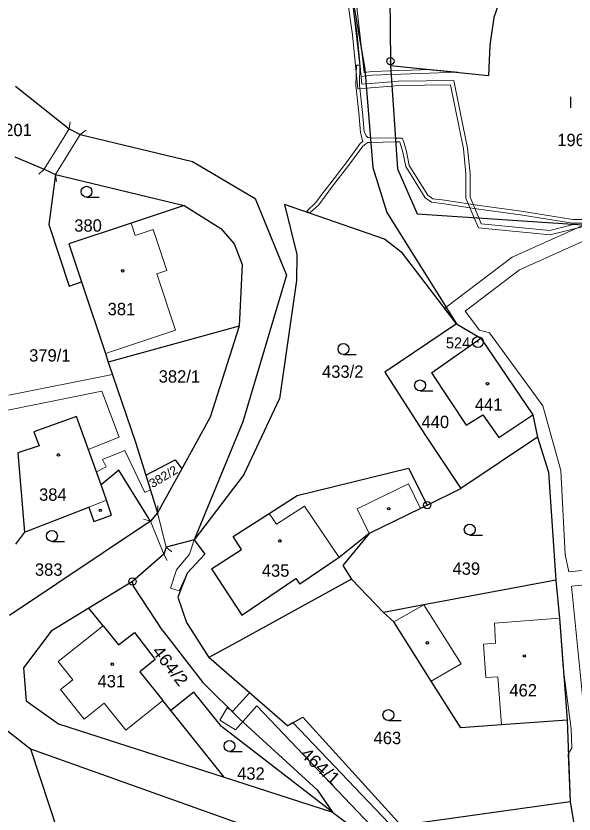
# Model space of a CAD drawing. Extents: x -727701 to -724405, y -960481 to -957284.
# Drawn here: x -726812.2 to -726735.5, y -958317.7 to -958207.9 of the extents above; entities that cross this region are included whole.
import ezdxf
from ezdxf.enums import TextEntityAlignment as Align

# ---------------------------------------------------------------- set-up
doc = ezdxf.new("R2010")
doc.units = 0
doc.header["$LTSCALE"] = 0.68
for name, color, linetype, lineweight in [('1', 7, 'Continuous', 25), ('13', 7, 'Continuous', 13), ('3', 7, 'Continuous', 25), ('4', 7, 'Continuous', 13), ('5', 7, 'Continuous', 25), ('8', 7, 'Continuous', 25)]:
    doc.layers.add(name, color=color, linetype=linetype, lineweight=lineweight)
doc.layers.add('2', color=7, linetype='Continuous')

msp = doc.modelspace()

# ---------------------------------------------------------------- linework, layer by layer
at = {"layer": '1'}
for p, q in [((-726767.89, -958194.1), (-726764.26, -958215.23)), ((-726760.86, -958201.3), (-726760.73, -958214.13)), ((-726744.52, -958202.36), (-726746.5, -958208.13)), ((-726746.5, -958208.13), (-726747.05, -958211.93)), ((-726747.05, -958211.93), (-726747.24, -958216.07)), ((-726760.73, -958214.13), (-726760.72, -958214.72)), ((-726764.26, -958215.23), (-726763.16, -958228.74)), ((-726760.72, -958214.72), (-726759.77, -958228.94)), ((-726760.72, -958214.72), (-726747.24, -958216.07)), ((-726812.27, -958217.58), (-726804.87, -958223.44)), ((-726804.87, -958223.44), (-726803.36, -958224.2)), ((-726803.36, -958224.2), (-726787.95, -958227.94)), ((-726812.38, -958227.27), (-726808.33, -958228.97)), ((-726787.95, -958227.94), (-726779.32, -958233.01)), ((-726808.33, -958228.97), (-726806.77, -958229.7)), ((-726763.16, -958228.74), (-726761.24, -958234.92)), ((-726759.77, -958228.94), (-726757.07, -958235.13)), ((-726806.77, -958229.7), (-726807.67, -958236.58)), ((-726806.77, -958229.7), (-726789.09, -958233.96)), ((-726779.32, -958233.01), (-726775.03, -958243.57)), ((-726775.3, -958233.84), (-726773.57, -958240.72)), ((-726761.56, -958238.62), (-726775.3, -958233.84)), ((-726789.09, -958233.96), (-726796.37, -958236.41)), ((-726789.09, -958233.96), (-726784.04, -958237.15)), ((-726761.24, -958234.92), (-726751.63, -958250.24)), ((-726757.07, -958235.13), (-726729.4, -958236.95)), ((-726807.67, -958236.58), (-726804.91, -958245.08)), ((-726796.37, -958236.41), (-726804.92, -958239.26)), ((-726784.04, -958237.15), (-726782.22, -958239.25)), ((-726804.92, -958239.26), (-726803.18, -958244.48)), ((-726782.22, -958239.25), (-726781.09, -958242.09)), ((-726759.08, -958240.55), (-726761.56, -958238.62)), ((-726773.57, -958240.72), (-726773.64, -958244.31)), ((-726751.63, -958250.24), (-726759.08, -958240.55)), ((-726781.09, -958242.09), (-726781.52, -958250.57)), ((-726775.03, -958243.57), (-726781, -958263.75)), ((-726804.91, -958245.08), (-726803.18, -958244.48)), ((-726803.18, -958244.48), (-726799.91, -958254.32)), ((-726773.64, -958244.31), (-726775.98, -958260.57)), ((-726751.63, -958250.24), (-726761.49, -958256.92)), ((-726751.63, -958250.24), (-726748.29, -958252.21)), ((-726781.52, -958250.57), (-726799.51, -958255.53)), ((-726781.52, -958250.57), (-726785.5, -958263.09)), ((-726755.1, -958257), (-726748.29, -958252.21)), ((-726748.29, -958252.21), (-726741.13, -958262.79)), ((-726799.91, -958254.32), (-726799.51, -958255.53)), ((-726799.51, -958255.53), (-726795.75, -958266.55)), ((-726761.49, -958256.92), (-726755.99, -958265.48)), ((-726755.1, -958257), (-726750.3, -958264.2)), ((-726780.83, -958270.92), (-726775.98, -958260.57)), ((-726803.89, -958263), (-726809.73, -958265.1)), ((-726800.51, -958272.39), (-726803.89, -958263)), ((-726785.5, -958263.09), (-726789.42, -958270.21)), ((-726750.3, -958264.2), (-726748, -958262.75)), ((-726748, -958262.75), (-726745.8, -958265.9)), ((-726745.8, -958265.9), (-726741.13, -958262.79)), ((-726741.13, -958262.79), (-726740.52, -958265.84)), ((-726781, -958263.75), (-726787.71, -958279.96)), ((-726809.73, -958265.1), (-726809, -958267.05)), ((-726755.99, -958265.48), (-726751.03, -958272.91)), ((-726795.75, -958266.55), (-726794.34, -958271.07)), ((-726740.52, -958265.84), (-726751.03, -958272.91)), ((-726740.52, -958265.84), (-726738.98, -958270.66)), ((-726809, -958267.05), (-726811.95, -958268)), ((-726811.95, -958268), (-726811.04, -958278.9)), ((-726794.34, -958271.07), (-726790.34, -958268.96)), ((-726790.34, -958268.96), (-726789.42, -958270.21)), ((-726773.53, -958273.85), (-726758.25, -958270.11)), ((-726798.04, -958270.4), (-726800.51, -958272.39)), ((-726793.71, -958277.41), (-726798.04, -958270.4)), ((-726794.34, -958271.07), (-726792.74, -958276.23)), ((-726789.42, -958270.21), (-726792.74, -958276.23)), ((-726780.83, -958270.92), (-726787.71, -958279.96)), ((-726738.98, -958270.66), (-726737.97, -958285.49)), ((-726799.75, -958274.5), (-726800.51, -958272.39)), ((-726799.05, -958276.57), (-726799.75, -958274.5)), ((-726777.38, -958276.34), (-726773.53, -958273.85)), ((-726811.04, -958278.9), (-726802.19, -958275.45)), ((-726802.19, -958275.45), (-726801.49, -958277.42)), ((-726755.66, -958275.2), (-726756.6, -958275.66)), ((-726801.49, -958277.42), (-726799.05, -958276.57)), ((-726792.74, -958276.23), (-726793.71, -958277.41)), ((-726782.33, -958279.52), (-726777.38, -958276.34)), ((-726756.6, -958275.66), (-726763.64, -958279.09)), ((-726793.71, -958277.41), (-726813.11, -958290.35)), ((-726811.04, -958278.9), (-726812.28, -958280.58)), ((-726787.71, -958279.96), (-726791.55, -958280.98)), ((-726787.71, -958279.96), (-726786.24, -958281.95)), ((-726781.19, -958281.29), (-726782.33, -958279.52)), ((-726763.64, -958279.09), (-726767.77, -958282.4)), ((-726763.64, -958279.09), (-726767.28, -958283.51)), ((-726791.55, -958280.98), (-726791.88, -958281.93)), ((-726791.88, -958281.93), (-726796.19, -958285.7)), ((-726786.24, -958281.95), (-726788.65, -958284.54)), ((-726785.33, -958283.97), (-726781.19, -958281.29)), ((-726767.77, -958282.4), (-726773.2, -958286.08)), ((-726785.33, -958283.97), (-726781.14, -958290.32)), ((-726767.28, -958283.51), (-726766.1, -958285.36)), ((-726788.65, -958284.54), (-726789.93, -958287.85)), ((-726766.1, -958285.36), (-726782, -958294.12)), ((-726781.14, -958290.32), (-726773.74, -958285.29)), ((-726773.74, -958285.29), (-726773.2, -958286.08)), ((-726761.7, -958289.95), (-726766.1, -958285.36)), ((-726737.97, -958285.49), (-726756.15, -958288.9)), ((-726737.97, -958285.49), (-726737.5, -958290.75)), ((-726796.19, -958285.7), (-726802.18, -958289.36)), ((-726796.04, -958286.33), (-726796.19, -958285.7)), ((-726792.01, -958292.47), (-726796.04, -958286.33)), ((-726789.93, -958287.85), (-726788.78, -958291.34)), ((-726802.18, -958289.36), (-726807.36, -958292.53)), ((-726800.22, -958291.79), (-726802.18, -958289.36)), ((-726756.15, -958288.9), (-726761.7, -958289.95)), ((-726760.26, -958291.26), (-726761.7, -958289.95)), ((-726737.5, -958290.75), (-726736.45, -958304.75)), ((-726800.22, -958291.79), (-726798.12, -958294.42)), ((-726788.78, -958291.34), (-726785.67, -958296.16)), ((-726757.39, -958295.84), (-726760.26, -958291.26)), ((-726807.36, -958292.53), (-726811.16, -958297.55)), ((-726798.12, -958294.42), (-726795.89, -958292.73)), ((-726795.89, -958292.73), (-726793.08, -958296.41)), ((-726792.01, -958292.47), (-726786.53, -958299.58)), ((-726782, -958294.12), (-726785.67, -958296.16)), ((-726793.08, -958296.41), (-726795.17, -958298.11)), ((-726774.89, -958305.53), (-726785.67, -958296.16)), ((-726755.11, -958299.4), (-726757.39, -958295.84)), ((-726811.16, -958297.55), (-726810.81, -958302.11)), ((-726795.17, -958298.11), (-726792, -958302.08)), ((-726786.53, -958299.58), (-726781.43, -958304.64)), ((-726751.04, -958305.84), (-726755.11, -958299.4)), ((-726787.74, -958300.92), (-726790.91, -958303.45)), ((-726783.97, -958305.64), (-726787.74, -958300.92)), ((-726810.81, -958302.11), (-726806.37, -958305.29)), ((-726790.91, -958303.45), (-726792, -958302.08)), ((-726783.58, -958312.63), (-726790.91, -958303.45)), ((-726814.98, -958304.97), (-726810.21, -958308.73)), ((-726781.43, -958304.64), (-726770.78, -958314.33)), ((-726774.89, -958305.53), (-726772.79, -958304.36)), ((-726772.79, -958304.36), (-726759.23, -958319.25)), ((-726736.45, -958304.75), (-726745.44, -958305.42)), ((-726736.45, -958304.75), (-726736.03, -958316.02)), ((-726806.37, -958305.29), (-726783.58, -958312.63)), ((-726768.67, -958317.43), (-726783.97, -958305.64)), ((-726745.44, -958305.42), (-726751.04, -958305.84)), ((-726810.21, -958308.73), (-726771.46, -958322.52)), ((-726810.21, -958308.73), (-726798.51, -958344.29)), ((-726783.58, -958312.63), (-726768.67, -958317.43)), ((-726770.78, -958314.33), (-726768.67, -958317.43)), ((-726736.03, -958316.02), (-726759.23, -958319.25)), ((-726736.03, -958316.02), (-726735.5, -958318.98)), ((-726768.67, -958317.43), (-726764.7, -958320.37))]:
    msp.add_line(p, q, dxfattribs=at)
msp.add_lwpolyline([(-726758.25, -958270.11), (-726755.66, -958275.2), (-726751.03, -958272.91)], dxfattribs=at)
at = {"layer": '13'}
for points in [[(-726766.72, -958205), (-726765.92, -958210.48), (-726765.2, -958217.94), (-726764.05, -958217.84), (-726760.53, -958217.54), (-726759.63, -958217.47), (-726752.48, -958217.38), (-726750.7, -958226.17), (-726750.38, -958229.63), (-726750.37, -958232.95), (-726749.23, -958235.65), (-726748.64, -958237.05), (-726738.78, -958238.02), (-726733.99, -958236.82)], [(-726735.41, -958236.55), (-726738.83, -958237.41), (-726748.23, -958236.49), (-726748.56, -958235.69), (-726749.77, -958232.83), (-726749.78, -958229.6), (-726750.11, -958226.08), (-726751.99, -958216.78), (-726759.66, -958216.87), (-726760.57, -958216.94), (-726764.1, -958217.25), (-726764.66, -958217.3), (-726765.32, -958210.4), (-726766.13, -958204.9)], [(-726765.88, -958206.35), (-726764.76, -958216.21), (-726763.21, -958216.05), (-726751.47, -958215.65), (-726755.2, -958215.27), (-726763.25, -958215.55)], [(-726763.25, -958215.55), (-726764.32, -958215.67), (-726765.38, -958206.27)], [(-726729.43, -958235.9), (-726735.66, -958235.91), (-726742.75, -958234.77), (-726748.47, -958233.98), (-726753.61, -958233.19), (-726754.88, -958233.04), (-726755.6, -958232.54), (-726758.14, -958228.45), (-726758.53, -958226.53), (-726758.89, -958225.26), (-726759.12, -958224.72), (-726760.05, -958224.7), (-726763.49, -958224.65), (-726763.81, -958224.64), (-726764.05, -958224.41), (-726764.35, -958223.81), (-726764.57, -958221.19), (-726765, -958217.4), (-726764.91, -958214.68), (-726765.41, -958214.66), (-726765.5, -958217.42), (-726765.07, -958221.23), (-726764.85, -958223.92), (-726764.52, -958225.17), (-726764.87, -958225.46), (-726766.55, -958227.74), (-726769.07, -958231.03), (-726770.12, -958232.39), (-726770.97, -958233.56), (-726772.21, -958234.75), (-726771.85, -958235.04), (-726770.59, -958233.88), (-726769.72, -958232.69), (-726768.67, -958231.33), (-726766.15, -958228.04), (-726764.51, -958225.8), (-726764.1, -958225.47), (-726763.84, -958225.33), (-726763.44, -958225.32), (-726760.02, -958225.23), (-726759.45, -958225.22), (-726759.37, -958225.42), (-726759.01, -958226.65), (-726758.62, -958228.63), (-726755.96, -958232.9), (-726755.06, -958233.52), (-726753.67, -958233.69), (-726748.55, -958234.48), (-726742.83, -958235.27), (-726735.7, -958236.41), (-726729.55, -958236.4)], [(-726734.11, -958236.64), (-726744, -958241.07), (-726753.05, -958247.98), (-726753.25, -958248.13), (-726751.63, -958250.24), (-726748.29, -958252.21), (-726741.13, -958262.79), (-726740.52, -958265.84), (-726738.98, -958270.66), (-726737.97, -958285.49), (-726737.5, -958290.75), (-726736.99, -958297.55), (-726735.89, -958305.96), (-726735.8, -958308.62), (-726736.28, -958309.4), (-726736.03, -958316.02), (-726735.5, -958318.98)], [(-726739.78, -958261.51), (-726747.09, -958251.48), (-726748.5, -958251.12), (-726750.45, -958248.51), (-726742.97, -958242.8), (-726731.16, -958237.51)], [(-726813.78, -958262.21), (-726800.4, -958259.53), (-726798.03, -958265.85), (-726802.26, -958267.53), (-726801.14, -958270.63), (-726799.79, -958269.94), (-726800.32, -958268.91), (-726797.25, -958267.69), (-726794.49, -958273.47), (-726793.71, -958273.1), (-726794.34, -958271.07), (-726795.75, -958266.55), (-726798.94, -958257.2), (-726813.2, -958260.06)], [(-726731.17, -958283.86), (-726736.2, -958284.37), (-726736.69, -958281.98), (-726737.3, -958270.44), (-726739.78, -958261.51)], [(-726734.01, -958304.67), (-726735.83, -958286.34), (-726731.74, -958285.93)], [(-726759.93, -958319.99), (-726774.12, -958305.1), (-726774.89, -958305.53), (-726780.12, -958300.99), (-726782.41, -958303.52), (-726783.18, -958303.07), (-726784.2, -958304.78), (-726782.03, -958306.08), (-726779.07, -958302.81), (-726761.52, -958321.23)]]:
    msp.add_lwpolyline(points, dxfattribs=at)
msp.add_lwpolyline([(-726787.71, -958279.96), (-726788.35, -958281.95), (-726790.14, -958284.11), (-726790.95, -958286.6), (-726789.77, -958286.99), (-726788.79, -958284.9), (-726788.65, -958284.54), (-726786.24, -958281.95)], close=True, dxfattribs=at)
at = {"layer": '3'}
for p, q in [((-726735.921, -958220.54), (-726735.921, -958219.04)), ((-726802.503, -958232.83), (-726800.753, -958232.83)), ((-726767.183, -958254.46), (-726765.433, -958254.46)), ((-726756.653, -958259.47), (-726754.903, -958259.47)), ((-726749.823, -958279.31), (-726748.073, -958279.31)), ((-726807.263, -958280.18), (-726805.513, -958280.18)), ((-726761.003, -958304.82), (-726759.253, -958304.82)), ((-726782.853, -958309.07), (-726781.103, -958309.07))]:
    msp.add_line(p, q, dxfattribs=at)
for centre in [(-726802.5029, -958232.0798), (-726767.1829, -958253.7098), (-726756.6529, -958258.7198), (-726749.8229, -958278.5598), (-726807.2629, -958279.4298), (-726761.0029, -958304.0698), (-726782.8529, -958308.3198)]:
    msp.add_circle(centre, 0.75, dxfattribs=at)
at = {"layer": '4'}
for p, q in [((-726804.765, -958222.445), (-726804.869, -958223.439)), ((-726804.87, -958223.44), (-726808.33, -958228.97)), ((-726802.55, -958223.612), (-726803.359, -958224.2)), ((-726806.77, -958229.7), (-726803.36, -958224.2)), ((-726809.038, -958229.677), (-726808.331, -958228.97)), ((-726806.614, -958230.688), (-726806.77, -958229.701)), ((-726796.37, -958236.41), (-726795.81, -958238.11)), ((-726795.81, -958238.11), (-726793.34, -958237.29)), ((-726793.34, -958237.29), (-726791.46, -958242.93)), ((-726791.46, -958242.93), (-726792.83, -958243.39)), ((-726792.83, -958243.39), (-726790.26, -958251.11)), ((-726790.26, -958251.11), (-726799.91, -958254.32)), ((-726765.3, -958275.68), (-726758.26, -958272.25)), ((-726758.26, -958272.25), (-726756.6, -958275.66)), ((-726802.19, -958275.45), (-726799.75, -958274.5)), ((-726792.722, -958275.23), (-726792.739, -958276.229)), ((-726776.37, -958277.81), (-726772.56, -958275.35)), ((-726772.56, -958275.35), (-726767.77, -958282.4)), ((-726792.74, -958276.23), (-726791.55, -958280.98)), ((-726777.38, -958276.34), (-726776.37, -958277.81)), ((-726763.64, -958279.09), (-726765.3, -958275.68)), ((-726794.672, -958277.134), (-726793.71, -958277.409)), ((-726791.88, -958281.93), (-726793.71, -958277.41)), ((-726790.762, -958281.596), (-726791.55, -958280.981)), ((-726791.411, -958282.814), (-726791.88, -958281.931)), ((-726760.26, -958291.26), (-726756.15, -958288.9)), ((-726756.15, -958288.9), (-726751.01, -958297.04)), ((-726746.44, -958291.42), (-726737.5, -958290.75)), ((-726806.39, -958296.71), (-726800.22, -958291.79)), ((-726746.28, -958294.18), (-726746.44, -958291.42)), ((-726747.95, -958294.3), (-726746.28, -958294.18)), ((-726747.61, -958298.92), (-726747.95, -958294.3)), ((-726806.39, -958296.71), (-726804.4, -958299.21)), ((-726751.01, -958297.04), (-726755.11, -958299.4)), ((-726804.4, -958299.21), (-726806.1, -958300.55)), ((-726745.94, -958298.79), (-726747.61, -958298.92)), ((-726745.44, -958305.42), (-726745.94, -958298.79)), ((-726802.85, -958304.62), (-726806.1, -958300.55)), ((-726800.1, -958302.42), (-726802.85, -958304.62)), ((-726797.11, -958306.16), (-726800.1, -958302.42)), ((-726792, -958302.08), (-726797.11, -958306.16))]:
    msp.add_line(p, q, dxfattribs=at)
at = {"layer": '5'}
for centre in [(-726797.5368, -958242.9592), (-726747.3868, -958258.4892), (-726806.3668, -958268.2792), (-726760.9568, -958275.6692), (-726800.6068, -958275.8992), (-726775.9168, -958280.1092), (-726755.6468, -958294.1292), (-726742.3168, -958295.9392), (-726798.9568, -958297.0592)]:
    msp.add_circle(centre, 0.175, dxfattribs=at)
at = {"layer": '8'}
for centre, radius in [((-726760.73, -958214.1299), 0.5), ((-726760.73, -958214.1299), 0.0303), ((-726748.7, -958252.7598), 0.75), ((-726748.7, -958252.7598), 0.03), ((-726755.66, -958275.1999), 0.5), ((-726755.66, -958275.1999), 0.0303), ((-726796.19, -958285.6999), 0.5), ((-726796.19, -958285.6999), 0.0303)]:
    msp.add_circle(centre, radius, dxfattribs=at)

# ---------------------------------------------------------------- texts
at = {"layer": '2'}
for s, p in [('201', (-726813.82, -958224.435)), ('196/1', (-726737.79, -958225.805)), ('380', (-726804.19, -958237.575)), ('381', (-726799.6, -958249.065)), ('382/1', (-726792.58, -958258.335)), ('441', (-726749.12, -958262.205)), ('440', (-726756.45, -958264.585)), ('384', (-726809.03, -958274.585)), ('383', (-726809.6, -958284.905)), ('435', (-726778.41, -958285.035)), ('439', (-726752.19, -958284.765)), ('431', (-726800.99, -958300.255)), ('462', (-726744.37, -958301.505)), ('463', (-726763.04, -958308.065)), ('432', (-726781.8, -958312.955))]:
    msp.add_text(s, height=1.7, dxfattribs=at).set_placement(p)
for s, p in [('379/1', (-726807.55, -958255.445)), ('433/2', (-726767.28, -958257.675))]:
    msp.add_text(s, height=1.7, dxfattribs=at).set_placement(p, align=Align.CENTER)
at = {"layer": '2', "width": 1.05}
msp.add_text('382/2', height=1.2, rotation=31, dxfattribs=at).set_placement((-726793.445, -958272.867))
at = {"layer": '2', "width": 1.1}
for s, rotation, p in [('464/2', 308, (-726791.6555, -958297.7977)), ('464/1', 318, (-726770.9248, -958311.7265))]:
    msp.add_text(s, height=1.7, rotation=rotation, dxfattribs=at).set_placement(p, align=Align.CENTER)
at = {"layer": '8'}
msp.add_text('524', height=1.5, dxfattribs=at).set_placement((-726753.1, -958253.625))

doc.saveas('drawing.dxf')
